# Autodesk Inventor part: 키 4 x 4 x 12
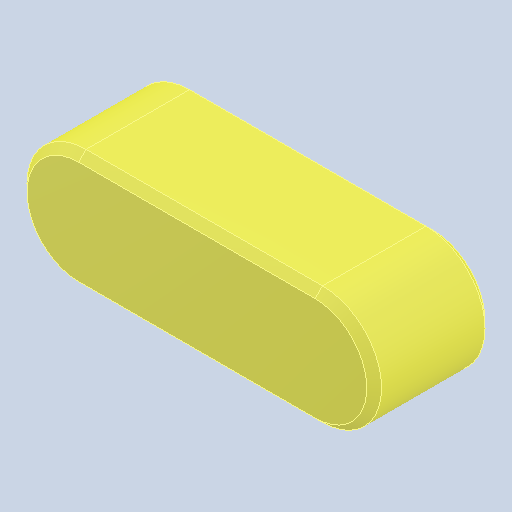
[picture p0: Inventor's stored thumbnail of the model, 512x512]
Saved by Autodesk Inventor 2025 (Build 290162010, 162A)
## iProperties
Created: 2024-07
Part Number: 키 4 x 4 x 12
Material: 강철, 연강
Description: 키 및 해당 키홈
Document SubType Name: Modeling
Designer: 학생
Density: 7.85 g/cm^3
Appearance: 기본값
Author: jhkim
Sending System: Autodesk Inventor 2025
Preprocessor: ST-DEVELOPER v20
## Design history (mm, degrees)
feature "Solid1"
node "솔리드1"
